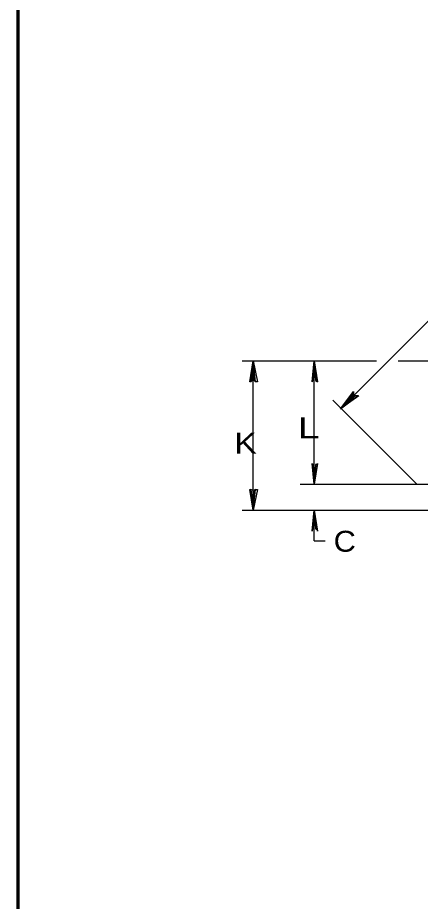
# Model space of a CAD drawing. Extents: x -0.018 to 0.195, y -0.006 to 0.263.
# Drawn here: x 0 to 0.0462, y 0.1026 to 0.2038 of the extents above; entities that cross this region are included whole.
import ezdxf
from ezdxf.enums import TextEntityAlignment as Align

# ---------------------------------------------------------------- set-up
doc = ezdxf.new("R2010")
doc.units = 0
doc.header["$LTSCALE"] = 0.00096
doc.linetypes.add('DOT_DASHED', pattern=[7.7, 5, -1.2, 0.3, -1.2])
doc.layers.add('1', color=7, linetype='Continuous', lineweight=25)

msp = doc.modelspace()

# ---------------------------------------------------------------- linework, layer by layer
at = {"layer": '1'}
for p, q in [((0.037, 0.159), (0.05738, 0.17938)), ((0.02575, 0.1645), (0.04113, 0.1645)), ((0.027, 0.14738), (0.027, 0.1645)), ((0.034, 0.15038), (0.034, 0.1645)), ((0.04362, 0.1645), (0.06237, 0.1645)), ((0.03612, 0.16), (0.04575, 0.15038)), ((0.02575, 0.14738), (0.06325, 0.14738)), ((0.034, 0.14388), (0.034, 0.14738)), ((0.034, 0.14388), (0.03525, 0.14388))]:
    msp.add_line(p, q, dxfattribs=at)
at = {"layer": '1', "linetype": 'DOT_DASHED'}
msp.add_line((0.03238, 0.15038), (0.14313, 0.15038), dxfattribs=at)
at = {"layer": '1', "lineweight": 70}
msp.add_lwpolyline([(0, 0), (0.1765, 0), (0.1765, 0.2565), (0, 0.2565)], close=True, dxfattribs=at)
at = {"layer": '1'}
for points in [[(0.02675, 0.16212), (0.02687, 0.16225), (0.027, 0.1645), (0.02675, 0.16212), (0.02662, 0.16212), (0.027, 0.1645), (0.02712, 0.16225), (0.02725, 0.16212), (0.027, 0.1645), (0.0275, 0.16212), (0.02725, 0.16212)], [(0.03375, 0.16212), (0.03388, 0.16225), (0.034, 0.1645), (0.03375, 0.16212), (0.03375, 0.16212), (0.034, 0.1645), (0.03413, 0.16225), (0.03438, 0.16212), (0.034, 0.1645), (0.03438, 0.16212), (0.03438, 0.16212)], [(0.039, 0.1605), (0.03875, 0.1605), (0.037, 0.159), (0.039, 0.1605), (0.03913, 0.1605), (0.037, 0.159), (0.03862, 0.16062), (0.0385, 0.16075), (0.037, 0.159), (0.0385, 0.161), (0.0385, 0.16075)], [(0.03438, 0.15263), (0.03413, 0.15263), (0.034, 0.15038), (0.03438, 0.15263), (0.03438, 0.15275), (0.034, 0.15038), (0.03388, 0.15263), (0.03375, 0.15263), (0.034, 0.15038), (0.03375, 0.15275), (0.03375, 0.15263)], [(0.02725, 0.14975), (0.02712, 0.14963), (0.027, 0.14738), (0.02725, 0.14975), (0.0275, 0.14975), (0.027, 0.14738), (0.027, 0.14963), (0.02675, 0.14975), (0.027, 0.14738), (0.02662, 0.14975), (0.02675, 0.14975)], [(0.03375, 0.14513), (0.03388, 0.14525), (0.034, 0.14738), (0.03375, 0.14513), (0.03375, 0.145), (0.034, 0.14738), (0.03413, 0.14525), (0.03438, 0.14513), (0.034, 0.14738), (0.03438, 0.145), (0.03438, 0.14513)]]:
    msp.add_lwpolyline(points, dxfattribs=at)

# ---------------------------------------------------------------- texts
for s, width, p in [('L', 1.4, (0.03338, 0.15563)), ('K', 1.2, (0.02612, 0.15388)), ('C', 1.1, (0.0375, 0.14263))]:
    msp.add_text(s, height=0.0024, dxfattribs=dict(at, width=width)).set_placement(p, align=Align.CENTER)

doc.saveas('drawing.dxf')
